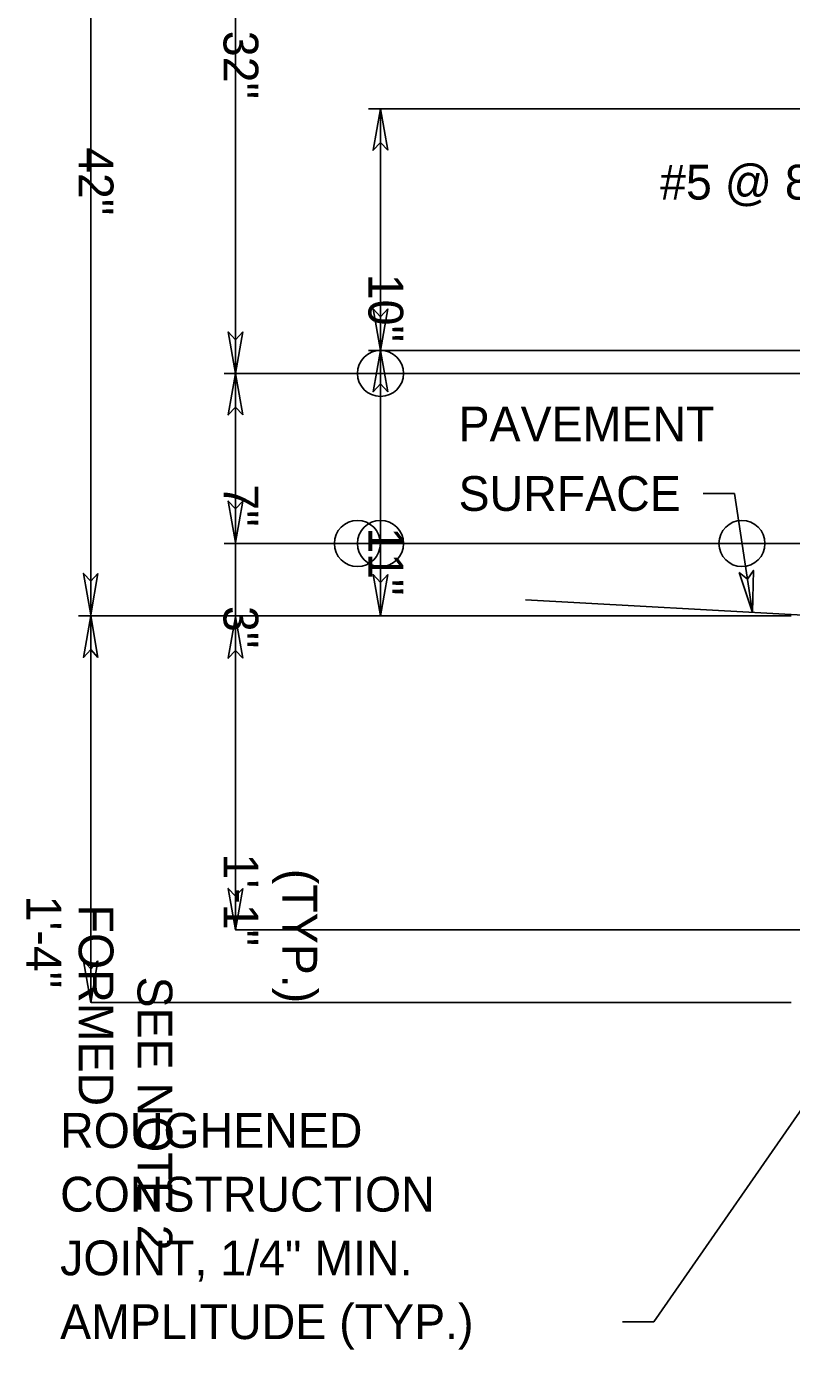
# Model space of a CAD drawing. Extents: x -26.46 to -19.21, y -3.62 to 6.25.
# Drawn here: x -25.101 to -23.781, y 1.399 to 3.682 of the extents above; entities that cross this region are included whole.
import ezdxf

# ---------------------------------------------------------------- set-up
doc = ezdxf.new("R2010")
doc.units = 0
for name, color, linetype in [('ANNO-WOUT', 7, 'Continuous'), ('DETL-DIMS', 7, 'Continuous'), ('Level 10', 7, 'Continuous'), ('Level 12', 7, 'Continuous'), ('SECT-GRND_P', 7, 'Continuous')]:
    doc.layers.add(name, color=color, linetype=linetype)

msp = doc.modelspace()

# ---------------------------------------------------------------- linework, layer by layer
at = {"layer": 'ANNO-WOUT'}
for centre in [(-24.4904, 3.0831), (-24.5302, 2.7896), (-24.4904, 2.7896), (-23.8667, 2.7896)]:
    msp.add_circle(centre, 0.0397, dxfattribs=at)
at = {"layer": 'DETL-DIMS'}
for p, q in [((-24.4904, 3.5396), (-24.5031, 3.4681)), ((-24.4904, 3.5396), (-24.4779, 3.4681)), ((-24.4904, 3.4816), (-24.5031, 3.4681)), ((-24.4779, 3.4681), (-24.4904, 3.4816)), ((-24.4904, 3.1229), (-24.5031, 3.1944)), ((-24.4904, 3.1809), (-24.5031, 3.1944)), ((-24.4904, 3.1229), (-24.4779, 3.1944)), ((-24.4779, 3.1944), (-24.4904, 3.1809)), ((-24.7404, 3.0831), (-24.7531, 3.1546)), ((-24.7404, 3.1411), (-24.7531, 3.1546)), ((-24.7404, 3.0831), (-24.7279, 3.1546)), ((-24.7279, 3.1546), (-24.7404, 3.1411)), ((-24.4904, 3.1229), (-24.5031, 3.0514)), ((-24.4904, 3.1229), (-24.4779, 3.0514)), ((-24.7404, 3.0831), (-24.7531, 3.0115)), ((-24.7404, 3.0831), (-24.7279, 3.0116)), ((-24.4904, 3.0649), (-24.5031, 3.0514)), ((-24.4779, 3.0514), (-24.4904, 3.0649)), ((-24.7404, 3.0251), (-24.7531, 3.0115)), ((-24.7279, 3.0116), (-24.7404, 3.0251)), ((-24.7404, 2.7914), (-24.7531, 2.8629)), ((-24.7404, 2.8494), (-24.7531, 2.8629)), ((-24.7404, 2.7914), (-24.7279, 2.8629)), ((-24.7279, 2.8629), (-24.7404, 2.8494)), ((-23.8573, 2.728), (-23.8468, 2.7432)), ((-23.8486, 2.6706), (-23.8468, 2.7432)), ((-24.9904, 2.6664), (-25.0031, 2.7379)), ((-24.9904, 2.7244), (-25.0031, 2.7379)), ((-24.9904, 2.6664), (-24.9779, 2.7379)), ((-24.9779, 2.7379), (-24.9904, 2.7244)), ((-24.4904, 2.6646), (-24.5031, 2.7361)), ((-24.4904, 2.7226), (-24.5031, 2.7361)), ((-24.4904, 2.6646), (-24.4779, 2.7361)), ((-24.4779, 2.7361), (-24.4904, 2.7226)), ((-23.8486, 2.6706), (-23.8717, 2.7394)), ((-23.8717, 2.7394), (-23.8573, 2.728)), ((-24.9904, 2.6646), (-25.0031, 2.5931)), ((-24.9904, 2.6646), (-24.9779, 2.5931)), ((-24.7404, 2.6632), (-24.7531, 2.5917)), ((-24.7404, 2.6632), (-24.7279, 2.5917)), ((-24.9904, 2.6066), (-25.0031, 2.5931)), ((-24.9779, 2.5931), (-24.9904, 2.6066)), ((-24.7404, 2.6052), (-24.7531, 2.5917)), ((-24.7279, 2.5917), (-24.7404, 2.6052)), ((-24.7404, 2.1229), (-24.7531, 2.1944)), ((-24.7404, 2.1809), (-24.7531, 2.1944)), ((-24.7404, 2.1229), (-24.7279, 2.1944)), ((-24.7279, 2.1944), (-24.7404, 2.1809)), ((-24.9904, 1.9979), (-25.0031, 2.0694)), ((-24.9904, 2.0559), (-25.0031, 2.0694)), ((-24.9904, 1.9979), (-24.9779, 2.0694)), ((-24.9779, 2.0694), (-24.9904, 2.0559))]:
    msp.add_line(p, q, dxfattribs=at)
for points in [[(-24.4779, 3.4681), (-24.4904, 3.5396), (-24.5031, 3.4681), (-24.4904, 3.4816)], [(-24.4779, 3.1944), (-24.4904, 3.1229), (-24.5031, 3.1944), (-24.4904, 3.1809)], [(-24.7279, 3.1546), (-24.7404, 3.0831), (-24.7531, 3.1546), (-24.7404, 3.1411)], [(-24.4779, 3.0514), (-24.4904, 3.1229), (-24.5031, 3.0514), (-24.4904, 3.0649)], [(-24.7279, 3.0116), (-24.7404, 3.0831), (-24.7531, 3.0115), (-24.7404, 3.0251)], [(-24.7279, 2.8629), (-24.7404, 2.7914), (-24.7531, 2.8629), (-24.7404, 2.8494)], [(-23.8717, 2.7394), (-23.8486, 2.6706), (-23.8468, 2.7432), (-23.8573, 2.728)], [(-24.9779, 2.7379), (-24.9904, 2.6664), (-25.0031, 2.7379), (-24.9904, 2.7244)], [(-24.4779, 2.7361), (-24.4904, 2.6646), (-24.5031, 2.7361), (-24.4904, 2.7226)], [(-24.9779, 2.5931), (-24.9904, 2.6646), (-25.0031, 2.5931), (-24.9904, 2.6066)], [(-24.7279, 2.5917), (-24.7404, 2.6632), (-24.7531, 2.5917), (-24.7404, 2.6052)], [(-24.7279, 2.1944), (-24.7404, 2.1229), (-24.7531, 2.1944), (-24.7404, 2.1809)], [(-24.9779, 2.0694), (-24.9904, 1.9979), (-25.0031, 2.0694), (-24.9904, 2.0559)]]:
    msp.add_lwpolyline(points, close=True, dxfattribs=at)
at = {"layer": 'Level 10'}
for p, q in [((-24.9904, 4.4164), (-24.9904, 2.6646)), ((-24.7404, 3.0845), (-24.7404, 4.4164)), ((-23.0321, 3.5396), (-24.5112, 3.5396)), ((-24.4904, 3.5396), (-24.4904, 3.1229)), ((-23.143, 3.1229), (-24.5112, 3.1229)), ((-24.4904, 2.6646), (-24.4904, 3.1229)), ((-24.7603, 3.0831), (-23.3422, 3.0831)), ((-24.7404, 2.7914), (-24.7404, 3.0845)), ((-23.9336, 2.8759), (-23.8797, 2.8759)), ((-23.8797, 2.8759), (-23.8486, 2.6706)), ((-24.7603, 2.7896), (-23.532, 2.7896)), ((-24.7404, 2.6646), (-24.7404, 2.7914)), ((-23.782, 2.6646), (-25.0112, 2.6646)), ((-24.9904, 2.6646), (-24.9904, 1.9979)), ((-23.782, 2.6646), (-24.9895, 2.6646)), ((-24.7404, 2.1229), (-24.7404, 2.6671)), ((-24.0188, 1.4469), (-23.1902, 2.64)), ((-23.4487, 2.1229), (-24.7395, 2.1229)), ((-23.782, 1.9979), (-24.9895, 1.9979)), ((-24.0727, 1.4469), (-24.0188, 1.4469))]:
    msp.add_line(p, q, dxfattribs=at)
at = {"layer": 'SECT-GRND_P'}
msp.add_line((-23.7404, 2.6646), (-24.2404, 2.6925), dxfattribs=at)

# ---------------------------------------------------------------- texts
at = {"layer": 'Level 12'}
for s, p in [('32"', (-24.7612, 3.6743)), ('42"', (-25.0112, 3.4736)), ('10"', (-24.5112, 3.2551)), ('7"', (-24.7612, 2.8918)), ('11"', (-24.5112, 2.8176)), ('3"', (-24.7612, 2.6818)), ('1\'-1"', (-24.7612, 2.2547)), ('(TYP.)', (-24.6596, 2.2283)), ('1\'-4"', (-25.1013, 2.1821)), ('FORMED', (-25.0112, 2.1666)), ('SEE NOTE 2', (-24.9096, 2.0424))]:
    msp.add_text(s, height=0.06001, rotation=270, dxfattribs=at).set_placement(p)
for s, p in [('#5 @ 8"', (-24.0079, 3.3831)), ('PAVEMENT ', (-24.3557, 2.9659)), ('SURFACE', (-24.3557, 2.8459)), ('ROUGHENED ', (-25.0432, 1.7469)), ('CONSTRUCTION ', (-25.0432, 1.6369)), ('JOINT, 1/4" MIN. ', (-25.0432, 1.5269)), ('AMPLITUDE (TYP.)', (-25.0432, 1.4169))]:
    msp.add_text(s, height=0.06001, dxfattribs=at).set_placement(p)

doc.saveas('drawing.dxf')
